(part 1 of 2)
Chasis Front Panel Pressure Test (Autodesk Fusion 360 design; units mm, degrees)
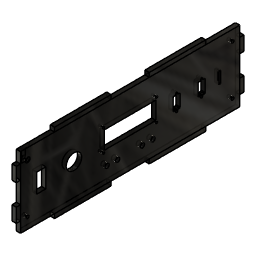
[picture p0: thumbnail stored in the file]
sketch "Sketch1" plane through (0, 0, 0) normal (1, 0, 0) x axis (0, 1, 0)
  line L1 (140.8306, 112.5808) -> (194.8306, 112.5808)
  line L2 (140.8306, 6.5808) -> (60.8306, 6.5808)
  line L3 (60.8306, 112.5808) -> (12.8306, 112.5808)
  line L4 (60.8306, 12.5808) -> (12.8306, 12.5808)
  line L5 (322.8306, 97.5808) -> (328.8306, 97.5808)
  line L6 (12.8306, 97.5808) -> (6.8306, 97.5808)
  line L7 (322.8306, 97.5808) -> (322.8306, 112.5808)
  line L8 (194.8306, 6.5808) -> (194.8306, 12.5808)
  line L9 (140.8306, 112.5808) -> (140.8306, 118.5808)
  line L10 (60.8306, 118.5808) -> (60.8306, 112.5808)
  line L11 (6.8306, 27.5808) -> (12.8306, 27.5808)
  line L12 (274.8306, 118.5808) -> (194.8306, 118.5808)
  line L13 (140.8306, 118.5808) -> (60.8306, 118.5808)
  line L14 (140.8306, 12.5808) -> (194.8306, 12.5808)
  line L15 (328.8306, 27.5808) -> (322.8306, 27.5808)
  line L16 (274.8306, 12.5808) -> (322.8306, 12.5808)
  line L17 (274.8306, 112.5808) -> (322.8306, 112.5808)
  line L18 (274.8306, 112.5808) -> (274.8306, 118.5808)
  line L19 (60.8306, 6.5808) -> (60.8306, 12.5808)
  line L20 (6.8306, 97.5808) -> (6.8306, 27.5808)
  line L21 (12.8306, 27.5808) -> (12.8306, 12.5808)
  line L22 (328.8306, 97.5808) -> (328.8306, 27.5808)
  line L23 (274.8306, 6.5808) -> (194.8306, 6.5808)
  line L24 (12.8306, 97.5808) -> (12.8306, 112.5808)
  line L25 (140.8306, 12.5808) -> (140.8306, 6.5808)
  line L26 (274.8306, 12.5808) -> (274.8306, 6.5808)
  line L27 (194.8306, 118.5808) -> (194.8306, 112.5808)
  line L28 (322.8306, 27.5808) -> (322.8306, 12.5808)
  line L29 (350, 62.5808) -> (328.8306, 62.5808)
  line L30 (167.8306, 0) -> (167.8306, 12.5808)
  point P34 (328.8306, 62.5808)
  point P36 (167.8306, 12.5808)
  point P26 (60.8306, 12.5808)
  point P27 (60.8306, 6.5808)
  point P8 (6.8306, 27.5808)
  point P20 (12.8306, 27.5808)
  point P3 (60.8306, 118.5808)
  point P10 (140.8306, 118.5808)
  point P6 (60.8306, 112.5808)
  point P9 (12.8306, 112.5808)
  point P19 (140.8306, 112.5808)
  point P23 (194.8306, 112.5808)
  point P32 (6.8306, 97.5808)
  point P16 (12.8306, 12.5808)
  point P2 (0, 0)
  point P1 (0, 0)
  point P37 (167.8306, 0)
  perpendicular L11 L21
  perpendicular L11 L20
  parallel L3 L13
  parallel L1 L3
  parallel L1 L12
  parallel L12 L17
  equal L9 L10
  equal L18 L27
  equal L5 L15
  equal L12 L13
  equal L21 L24
  parallel L2 L13
  parallel L12 L23
  parallel L16 L17
  parallel L1 L14
  parallel L21 L28
  parallel L7 L24
  equal L3 L17
  equal L10 L27
  equal L20 L22
  equal L7 L24
  equal L21 L28
  collinear L4 L14
  collinear L14 L16
  collinear L12 L13
  collinear L1 L3
  collinear L1 L17
  collinear L2 L23
  collinear L5 L6
  collinear L11 L15
  perpendicular L3 L24
  perpendicular L4 L21
  vertical L24
  midpoint L22 P34
  perpendicular L22 L29
  midpoint L14 P36
  perpendicular L14 L30
  dimension "d42" distance P26 P27 = 6
  dimension "d43" distance P8 P20 = 6
  dimension "d44" distance L20 L22 = 322
  dimension "d45" distance P3 P10 = 80
  dimension "d46" distance P6 P9 = 48
  dimension "d47" distance P19 P23 = 54
  dimension "d48" distance P3 P6 = 6
  dimension "d49" distance L16 L17 = 100
  dimension "d50" distance P8 P32 = 70
  dimension "d51" distance P16 P20 = 15
  dimension "d192" distance P2 L22 = 328.8306
  dimension "d195" distance P2 L29 = 62.5808
  dimension "d198" distance P1 P37 = 167.8306
extrude "Extrude3" new body sketch "Sketch1" profile of L1 L2 L3 L4 L5 L6 L7 L8 L9 L10 L11 L12 L13 L14 L15 L16 L17 L18 L19 L20 L21 L22 L23 L24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 along normal blind 6
sketch "Sketch2" plane through (6, 0, 0) normal (1, 0, 0) x axis (0, 1, 0)
  line L1 (194.8306, 6.5808) -> (194.8306, 12.5808)
  line L2 (274.8306, 6.5808) -> (194.8306, 6.5808)
  line L3 (274.8306, 12.5808) -> (274.8306, 6.5808)
  line L4 (322.8306, 12.5808) -> (274.8306, 12.5808)
  line L5 (322.8306, 27.5808) -> (322.8306, 12.5808)
  line L6 (328.8306, 27.5808) -> (322.8306, 27.5808)
  line L7 (328.8306, 97.5808) -> (328.8306, 27.5808)
  line L8 (322.8306, 97.5808) -> (328.8306, 97.5808)
  line L9 (322.8306, 112.5808) -> (322.8306, 97.5808)
  line L10 (274.8306, 112.5808) -> (322.8306, 112.5808)
  line L11 (274.8306, 118.5808) -> (274.8306, 112.5808)
  line L12 (194.8306, 118.5808) -> (274.8306, 118.5808)
  line L13 (194.8306, 112.5808) -> (194.8306, 118.5808)
  line L14 (140.8306, 112.5808) -> (194.8306, 112.5808)
  line L15 (140.8306, 118.5808) -> (140.8306, 112.5808)
  line L16 (60.8306, 118.5808) -> (140.8306, 118.5808)
  line L17 (60.8306, 112.5808) -> (60.8306, 118.5808)
  line L18 (12.8306, 112.5808) -> (60.8306, 112.5808)
  line L19 (12.8306, 97.5808) -> (12.8306, 112.5808)
  line L20 (6.8306, 97.5808) -> (12.8306, 97.5808)
  line L21 (6.8306, 27.5808) -> (6.8306, 97.5808)
  line L22 (12.8306, 27.5808) -> (6.8306, 27.5808)
  line L23 (12.8306, 12.5808) -> (12.8306, 27.5808)
  line L24 (60.8306, 12.5808) -> (12.8306, 12.5808)
  line L25 (60.8306, 6.5808) -> (60.8306, 12.5808)
  line L26 (140.8306, 6.5808) -> (60.8306, 6.5808)
  line L27 (140.8306, 12.5808) -> (140.8306, 6.5808)
  line L28 (194.8306, 12.5808) -> (140.8306, 12.5808)
  line L29 (204.3306, 80.0808) -> (131.3306, 80.0808)
  line L30 (204.3306, 55.0808) -> (204.3306, 80.0808)
  line L31 (131.3306, 55.0808) -> (204.3306, 55.0808)
  line L32 (131.3306, 80.0808) -> (131.3306, 55.0808)
  line L33 (48.6306, 76.0808) -> (35.6306, 76.0808)
  line L34 (48.6306, 49.0808) -> (48.6306, 76.0808)
  line L35 (35.6306, 49.0808) -> (48.6306, 49.0808)
  line L36 (35.6306, 76.0808) -> (35.6306, 49.0808)
  line L37 (167.8306, 12.5808) -> (167.8306, 112.5808)
  line L38 (6.8306, 62.5808) -> (328.8306, 62.5808)
  line L39 (204.3306, 55.0808) -> (131.3306, 80.0808)
  line L40 (204.3306, 80.0808) -> (131.3306, 55.0808)
  line L41 (167.8306, 55.0808) -> (167.8306, 80.0808)
  line L42 (204.3306, 67.5808) -> (131.3306, 67.5808)
  line L43 (99.4306, 62.5808) -> (88.4306, 62.5808)
  line L44 (48.6306, 62.5808) -> (35.6306, 62.5808)
  line L45 (185.3306, 33.8308) -> (150.3306, 33.8308)
  line L46 (167.8306, 44.7562) -> (167.8306, 33.8308)
  line L47 (130.3306, 83.0808) -> (205.3306, 83.0808)
  line L48 (130.3306, 52.0808) -> (130.3306, 83.0808)
  line L49 (205.3306, 52.0808) -> (130.3306, 52.0808)
  line L50 (205.3306, 83.0808) -> (205.3306, 52.0808)
  line L51 (130.3306, 52.0808) -> (205.3306, 83.0808)
  line L52 (205.3306, 52.0808) -> (130.3306, 83.0808)
  line L53 (351.4437, 121.1972) -> (351.4437, 118.8472)
  line L54 (351.4437, 115.8472) -> (351.4437, 113.4972)
  line L55 (351.4437, 115.8472) -> (349.7937, 115.8472)
  line L56 (370.1437, 121.1972) -> (370.1437, 118.8472)
  line L57 (351.4437, 118.8472) -> (349.7937, 118.8472)
  line L58 (360.7937, 122.2972) -> (360.7937, 117.3472)
  line L59 (349.7937, 117.3472) -> (360.7937, 117.3472)
  line L60 (370.1437, 115.8472) -> (370.1437, 113.4972)
  line L61 (369.0437, 122.2972) -> (352.5437, 122.2972)
  line L62 (352.5437, 112.3972) -> (369.0437, 112.3972)
  line L63 (370.1437, 115.8472) -> (371.7937, 115.8472)
  line L64 (370.1437, 118.8472) -> (371.7937, 118.8472)
  line L65 (348.2937, 117.3472) -> (349.7937, 117.3472)
  line L66 (373.2937, 117.3472) -> (371.7937, 117.3472)
  line L67 (272.9555, 53.2308) -> (270.6055, 53.2308)
  line L68 (274.0555, 54.3308) -> (274.0555, 70.8308)
  line L69 (272.9555, 71.9308) -> (270.6055, 71.9308)
  line L70 (269.1055, 75.0808) -> (269.1055, 73.5808)
  line L71 (267.6055, 53.2308) -> (265.2555, 53.2308)
  line L72 (270.6055, 53.2308) -> (270.6055, 51.5808)
  line L73 (270.6055, 71.9308) -> (270.6055, 73.5808)
  line L74 (267.6055, 53.2308) -> (267.6055, 51.5808)
  line L75 (269.1055, 50.0808) -> (269.1055, 51.5808)
  line L76 (267.6055, 71.9308) -> (265.2555, 71.9308)
  line L77 (274.0555, 62.5808) -> (269.1055, 62.5808)
  line L78 (267.6055, 71.9308) -> (267.6055, 73.5808)
  line L79 (264.1555, 70.8308) -> (264.1555, 54.3308)
  line L80 (269.1055, 73.5808) -> (269.1055, 62.5808)
  line L81 (295.8805, 70.6308) -> (293.4805, 70.6308)
  line L82 (295.8805, 54.5308) -> (295.8805, 70.6308)
  line L83 (293.4805, 54.5308) -> (295.8805, 54.5308)
  line L84 (293.4805, 70.6308) -> (293.4805, 54.5308)
  line L85 (269.1055, 75.0808) -> (269.1055, 73.5808)
  line L86 (272.9555, 71.9308) -> (270.6055, 71.9308)
  line L87 (269.1055, 50.0808) -> (269.1055, 51.5808)
  line L88 (272.9555, 53.2308) -> (270.6055, 53.2308)
  line L89 (269.1055, 73.5808) -> (269.1055, 62.5808)
  line L90 (274.0555, 62.5808) -> (269.1055, 62.5808)
  line L91 (267.6055, 53.2308) -> (265.2555, 53.2308)
  line L92 (270.6055, 71.9308) -> (270.6055, 73.5808)
  line L93 (267.6055, 71.9308) -> (265.2555, 71.9308)
  line L94 (267.6055, 71.9308) -> (267.6055, 73.5808)
  line L95 (270.6055, 53.2308) -> (270.6055, 51.5808)
  line L96 (274.0555, 54.3308) -> (274.0555, 70.8308)
  line L97 (264.1555, 70.8308) -> (264.1555, 54.3308)
  line L98 (267.6055, 53.2308) -> (267.6055, 51.5808)
  line L99 (295.8805, 62.5808) -> (293.4805, 62.5808)
  line L100 (294.6805, 70.6308) -> (294.6805, 54.5308)
  line L101 (228.6805, 70.8308) -> (228.6805, 54.3308)
  line L102 (233.6305, 73.5808) -> (233.6305, 62.5808)
  line L103 (237.4805, 71.9308) -> (235.1305, 71.9308)
  line L104 (232.1305, 71.9308) -> (232.1305, 73.5808)
  line L105 (238.5805, 54.3308) -> (238.5805, 70.8308)
  line L106 (232.1305, 71.9308) -> (232.1305, 73.5808)
  line L107 (228.6805, 70.8308) -> (228.6805, 54.3308)
  line L108 (238.5805, 62.5808) -> (233.6305, 62.5808)
  line L109 (232.1305, 71.9308) -> (229.7805, 71.9308)
  line L110 (238.5805, 54.3308) -> (238.5805, 70.8308)
  line L111 (232.1305, 71.9308) -> (229.7805, 71.9308)
  line L112 (233.6305, 75.0808) -> (233.6305, 73.5808)
  line L113 (232.1305, 53.2308) -> (229.7805, 53.2308)
  line L114 (232.1305, 53.2308) -> (229.7805, 53.2308)
  line L115 (233.6305, 50.0808) -> (233.6305, 51.5808)
  line L116 (237.4805, 71.9308) -> (235.1305, 71.9308)
  line L117 (233.6305, 75.0808) -> (233.6305, 73.5808)
  line L118 (232.1305, 53.2308) -> (232.1305, 51.5808)
  line L119 (235.1305, 71.9308) -> (235.1305, 73.5808)
  line L120 (235.1305, 71.9308) -> (235.1305, 73.5808)
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  point P43 (167.8306, 112.5808)
  point P44 (167.8306, 12.5808)
  point P45 (328.8306, 62.5808)
  point P46 (6.8306, 62.5808)
  point P47 (167.8306, 80.0808)
  point P48 (167.8306, 55.0808)
  point P49 (131.3306, 67.5808)
  point P50 (204.3306, 67.5808)
  point P42 (88.4306, 62.5808)
  point P51 (88.4306, 62.5808)
  point P53 (35.6306, 62.5808)
  point P54 (48.6306, 62.5808)
  point P35 (150.3306, 33.8308)
  point P55 (150.3306, 33.8308)
  point P36 (185.3306, 33.8308)
  point P56 (185.3306, 33.8308)
  point P57 (167.8306, 33.8308)
  point P63 (167.8306, 67.5808)
  point P59 (205.3306, 83.0808)
  point P64 (205.3306, 83.0808)
  point P62 (205.3306, 52.0808)
  point P65 (205.3306, 52.0808)
  point P60 (130.3306, 83.0808)
  point P66 (130.3306, 83.0808)
  point P61 (130.3306, 52.0808)
  point P67 (130.3306, 52.0808)
  point P94 (360.7937, 117.3472)
  point P96 (360.7937, 117.3472)
  point P68 (349.7937, 117.3472)
  point P95 (349.7937, 117.3472)
  point P69 (349.7937, 117.3472)
  point P80 (360.7937, 122.2972)
  point P77 (351.4437, 121.1972)
  point P92 (370.1437, 121.1972)
  point P83 (351.4437, 113.4972)
  point P89 (370.1437, 113.4972)
  point P72 (349.7937, 118.8472)
  point P93 (371.7937, 118.8472)
  point P76 (351.4437, 118.8472)
  point P90 (370.1437, 118.8472)
  point P79 (349.7937, 115.8472)
  point P87 (371.7937, 115.8472)
  point P70 (351.4437, 115.8472)
  point P91 (370.1437, 115.8472)
  point P97 (349.7937, 117.3472)
  point P88 (371.7937, 117.3472)
  point P99 (371.7937, 117.3472)
  point P119 (269.1055, 62.5808)
  point P128 (269.1055, 62.5808)
  point P107 (269.1055, 73.5808)
  point P127 (269.1055, 73.5808)
  point P101 (269.1055, 73.5808)
  point P112 (274.0555, 62.5808)
  point P110 (272.9555, 71.9308)
  point P124 (272.9555, 53.2308)
  point P116 (265.2555, 71.9308)
  point P121 (265.2555, 53.2308)
  point P106 (270.6055, 73.5808)
  point P118 (270.6055, 51.5808)
  point P104 (270.6055, 71.9308)
  point P122 (270.6055, 53.2308)
  point P111 (267.6055, 73.5808)
  point P125 (267.6055, 51.5808)
  point P108 (267.6055, 71.9308)
  point P126 (267.6055, 53.2308)
  point P130 (269.1055, 73.5808)
  point P123 (269.1055, 51.5808)
  point P132 (269.1055, 51.5808)
  point P149 (269.1055, 62.5808)
  point P168 (269.1055, 62.5808)
  point P142 (269.1055, 73.5808)
  point P158 (269.1055, 73.5808)
  point P162 (269.1055, 73.5808)
  point P151 (274.0555, 62.5808)
  point P139 (272.9555, 53.2308)
  point P146 (272.9555, 71.9308)
  point P143 (265.2555, 53.2308)
  point P155 (265.2555, 71.9308)
  point P148 (270.6055, 51.5808)
  point P156 (270.6055, 73.5808)
  point P144 (270.6055, 53.2308)
  point P163 (270.6055, 71.9308)
  point P145 (267.6055, 51.5808)
  point P150 (267.6055, 73.5808)
  point P141 (267.6055, 53.2308)
  point P159 (267.6055, 71.9308)
  point P165 (269.1055, 73.5808)
  point P138 (269.1055, 51.5808)
  point P167 (269.1055, 51.5808)
  point P171 (293.4805, 62.5808)
  point P172 (295.8805, 62.5808)
  point P173 (294.6805, 54.5308)
  point P174 (294.6805, 70.6308)
  point P186 (233.6305, 62.5808)
  point P205 (233.6305, 62.5808)
  point P179 (233.6305, 73.5808)
  point P195 (233.6305, 73.5808)
  point P199 (233.6305, 73.5808)
  point P188 (238.5805, 62.5808)
  point P202 (233.6305, 73.5808)
  point P175 (233.6305, 51.5808)
  point P204 (233.6305, 51.5808)
  point P213 (233.6305, 62.5808)
  point P226 (233.6305, 62.5808)
  point P209 (233.6305, 73.5808)
  point P227 (233.6305, 73.5808)
  point P230 (233.6305, 73.5808)
  point P238 (238.5805, 62.5808)
  point P232 (237.4805, 53.2308)
  point P236 (237.4805, 71.9308)
  point P217 (229.7805, 53.2308)
  point P220 (229.7805, 71.9308)
  point P223 (235.1305, 73.5808)
  point P231 (235.1305, 51.5808)
  point P207 (235.1305, 71.9308)
  point P229 (235.1305, 53.2308)
  point P208 (232.1305, 51.5808)
  point P214 (232.1305, 73.5808)
  point P216 (232.1305, 71.9308)
  point P235 (232.1305, 53.2308)
  point P219 (233.6305, 73.5808)
  point P212 (233.6305, 51.5808)
  point P225 (233.6305, 51.5808)
  point P241 (204.3306, 62.5808)
  point P243 (233.6305, 62.5808)
  point P30 (131.3306, 80.0808)
  point P31 (204.3306, 80.0808)
  point P33 (131.3306, 55.0808)
  point P34 (135.3306, 33.8308)
  point P37 (200.3306, 33.8308)
  point P38 (35.6306, 76.0808)
  point P39 (48.6306, 76.0808)
  point P41 (35.6306, 49.0808)
  point P78 (352.5437, 122.2972)
  point P86 (369.0437, 122.2972)
  point P98 (348.2937, 117.3472)
  point P100 (373.2937, 117.3472)
  point P115 (274.0555, 70.8308)
  point P120 (274.0555, 54.3308)
  point P131 (269.1055, 75.0808)
  point P133 (269.1055, 50.0808)
  point P134 (293.4805, 70.6308)
  point P135 (295.8805, 70.6308)
  point P137 (293.4805, 54.5308)
  point P140 (274.0555, 54.3308)
  point P154 (274.0555, 70.8308)
  point P169 (269.1055, 75.0808)
  point P170 (269.1055, 50.0808)
  point P183 (237.4805, 71.9308)
  point P200 (235.1305, 71.9308)
  point P177 (238.5805, 54.3308)
  point P191 (238.5805, 70.8308)
  point P206 (233.6305, 75.0808)
  point P222 (233.6305, 50.0808)
  point P218 (238.5805, 70.8308)
  point P233 (238.5805, 54.3308)
  point P228 (233.6305, 75.0808)
  point P240 (233.6305, 50.0808)
  point P242 (229.9056, 62.5808)
  horizontal L29
  vertical L30
  horizontal L31
  vertical L32
  horizontal L33
  vertical L34
  horizontal L35
  vertical L36
  midpoint L14 P43
  midpoint L28 P44
  midpoint L7 P45
  midpoint L21 P46
  midpoint L29 P47
  midpoint L31 P48
  midpoint L32 P49
  midpoint L30 P50
  coincident P42 P51
  horizontal L43
  collinear L38 L43
  midpoint L36 P53
  midpoint L34 P54
  collinear L38 L44
  coincident P35 P55
  coincident P36 P56
  parallel L26 L45
  midpoint L45 P57
  perpendicular L45 L46
  collinear L37 L46
  collinear L37 L41
  horizontal L47
  perpendicular L47 L48
  parallel L47 L49
  parallel L48 L50
  coincident L51 P63
  coincident L52 P63
  midpoint L39 P63
  coincident P59 P64
  coincident P62 P65
  coincident P60 P66
  coincident P61 P67
  horizontal L62
  parallel L61 L62
  coincident P94 P96
  coincident P68 P95
  coincident P68 P69
  midpoint P80 L61
  perpendicular L58 L61
  symmetric P77 P92 L58
  symmetric P83 P89 L58
  symmetric P72 P93 L58
  symmetric P76 P90 L58
  symmetric P79 P87 L58
  symmetric P70 P91 L58
  equal L53 L54
  equal L61 L62
  coincident P68 P97
  parallel L59 L65
  coincident P88 P99
  perpendicular L56 L66
  parallel L68 L79
  coincident P119 P128
  coincident P107 P127
  coincident P101 P107
  midpoint P112 L68
  perpendicular L68 L77
  symmetric P110 P124 L77
  symmetric P116 P121 L77
  symmetric P106 P118 L77
  symmetric P104 P122 L77
  symmetric P111 P125 L77
  symmetric P108 P126 L77
  equal L69 L76
  equal L68 L79
  coincident P107 P130
  parallel L70 L80
  coincident P123 P132
  perpendicular L67 L75
  horizontal L81
  vertical L82
  horizontal L83
  vertical L84
  parallel L96 L97
  coincident P149 P168
  coincident P142 P158
  coincident P158 P162
  midpoint P151 L96
  perpendicular L90 L96
  symmetric P139 P146 L90
  symmetric P143 P155 L90
  symmetric P148 P156 L90
  symmetric P144 P163 L90
  symmetric P145 P150 L90
  symmetric P141 P159 L90
  equal L86 L93
  equal L96 L97
  coincident P158 P165
  parallel L85 L89
  coincident P138 P167
  perpendicular L87 L88
  midpoint L84 P171
  midpoint L82 P172
  collinear L77 L99
  midpoint L83 P173
  midpoint L81 P174
  parallel L105 L107
  coincident P186 P205
  coincident P179 P195
  coincident P195 P199
  midpoint P188 L105
  equal L103 L109
  equal L105 L107
  coincident P195 P202
  parallel L102 L112
  coincident P175 P204
  parallel L101 L110
  coincident P213 P226
  coincident P209 P227
  coincident P227 P230
  midpoint P238 L110
  perpendicular L108 L110
  symmetric P232 P236 L108
  symmetric P217 P220 L108
  symmetric P223 P231 L108
  symmetric P207 P229 L108
  symmetric P208 P214 L108
  symmetric P216 P235 L108
  equal L111 L116
  equal L101 L110
  coincident P219 P227
  coincident P212 P225
  coincident L30 P241
  coincident L38 P241
  coincident P213 P243
  dimension "d56" distance P30 P31 = 73
  dimension "d57" distance P30 P33 = 25
  dimension "d58" diameter = 6
  dimension "d59" diameter = 6
  dimension "d60" distance P34 P35 = 15
  dimension "d61" diameter = 6
  dimension "d62" diameter = 6
  dimension "d63" distance P36 P37 = 15
  dimension "d64" distance P35 P36 = 35
  dimension "d65" distance P38 P39 = 13
  dimension "d66" distance P38 P41 = 27
  dimension "d67" diameter = 22
  dimension "d68" distance L31 L45 = 21.25 (= "d75 / 2")
  dimension "d69" distance L38 L42 = 5
  dimension "d73" distance L21 L36 = 28.8
  dimension "d74" distance L34 P42 = 39.8 (= "28.8 mm + 11 mm")
  dimension "d75" distance L28 L31 = 42.5
  dimension "d76" distance P61 P62 = 75
  dimension "d77" distance P60 P61 = 31
  dimension "d78" diameter = 3
  dimension "d79" diameter = 3
  dimension "d80" diameter = 3
  dimension "d81" diameter = 3
  dimension "d82" distance P95 P96 = 11
  dimension "d83" diameter = 3
  dimension "d84" distance L59 L61 = 4.95
  dimension "d85" distance P76 P77 = 2.35
  dimension "d86" radius = 1.1
  dimension "d87" distance P78 P86 = 16.5
  dimension "d88" distance L54 L60 = 18.7
  dimension "d89" distance P69 P88 = 22
  dimension "d90" distance L61 L62 = 9.9
  dimension "d91" distance P98 P100 = 25
  dimension "d92" distance P127 P128 = 11
  dimension "d93" diameter = 3
  dimension "d94" distance L68 L80 = 4.95
  dimension "d95" distance P104 P110 = 2.35
  dimension "d96" radius = 1.1
  dimension "d97" distance P115 P120 = 16.5
  dimension "d98" distance L71 L76 = 18.7
  dimension "d99" distance P101 P123 = 22
  dimension "d100" distance L68 L79 = 9.9
  dimension "d101" distance P131 P133 = 25
  dimension "d102" distance P134 P135 = 2.4
  dimension "d103" distance P134 P137 = 16.1
  dimension "d104" distance P142 P168 = 11
  dimension "d105" diameter = 3
  dimension "d106" distance L89 L96 = 4.95
  dimension "d107" distance P146 P163 = 2.35
  dimension "d108" radius = 1.1
  dimension "d109" distance P140 P154 = 16.5
  dimension "d110" distance L91 L93 = 18.7
  dimension "d111" distance P138 P162 = 22
  dimension "d112" distance L96 L97 = 9.9
  dimension "d113" distance P169 P170 = 25
  dimension "d125" distance L89 L100 = 25.575
  dimension "d126" distance P179 P205 = 11
  dimension "d127" diameter = 3
  dimension "d128" distance L102 L105 = 4.95
  dimension "d129" distance P183 P200 = 2.35
  dimension "d130" radius = 1.1
  dimension "d131" distance P177 P191 = 16.5
  dimension "d132" distance L109 L113 = 18.7
  dimension "d133" distance P175 P199 = 22
  dimension "d134" distance L105 L107 = 9.9
  dimension "d135" distance P206 P222 = 25
  dimension "d136" distance P209 P226 = 11
  dimension "d137" diameter = 3
  dimension "d138" distance = 4.95
  dimension "d139" distance P207 P236 = 2.35
  dimension "d140" radius = 1.1
  dimension "d141" distance P218 P233 = 16.5
  dimension "d142" distance L111 L114 = 18.7
  dimension "d143" distance P212 P230 = 22
  dimension "d144" distance L101 L110 = 9.9
  dimension "d145" distance P228 P240 = 25
  dimension "d146" distance L80 L102 = 35.475
  dimension "d147" distance P241 P242 = 25.575
extrude "Extrude4" cut sketch "Sketch2" against normal blind 6
sketch "Sketch4" plane through (6, 0, 0) normal (1, 0, 0) x axis (0, 1, 0)
  line L1 (12.8306, 27.5808) -> (6.8306, 27.5808)
  line L2 (12.8306, 12.5808) -> (12.8306, 27.5808)
  line L3 (60.8306, 12.5808) -> (12.8306, 12.5808)
  line L4 (60.8306, 6.5808) -> (60.8306, 12.5808)
  line L5 (140.8306, 6.5808) -> (60.8306, 6.5808)
  line L6 (140.8306, 12.5808) -> (140.8306, 6.5808)
  line L7 (194.8306, 12.5808) -> (140.8306, 12.5808)
  line L8 (194.8306, 6.5808) -> (194.8306, 12.5808)
  line L9 (274.8306, 6.5808) -> (194.8306, 6.5808)
  line L10 (274.8306, 12.5808) -> (274.8306, 6.5808)
  line L11 (322.8306, 12.5808) -> (274.8306, 12.5808)
  line L12 (322.8306, 27.5808) -> (322.8306, 12.5808)
  line L13 (328.8306, 27.5808) -> (322.8306, 27.5808)
  line L14 (328.8306, 97.5808) -> (328.8306, 27.5808)
  line L15 (322.8306, 97.5808) -> (328.8306, 97.5808)
  line L16 (322.8306, 112.5808) -> (322.8306, 97.5808)
  line L17 (274.8306, 112.5808) -> (322.8306, 112.5808)
  line L18 (274.8306, 118.5808) -> (274.8306, 112.5808)
  line L19 (194.8306, 118.5808) -> (274.8306, 118.5808)
  line L20 (194.8306, 112.5808) -> (194.8306, 118.5808)
  line L21 (140.8306, 112.5808) -> (194.8306, 112.5808)
  line L22 (140.8306, 118.5808) -> (140.8306, 112.5808)
  line L23 (60.8306, 118.5808) -> (140.8306, 118.5808)
  line L24 (60.8306, 112.5808) -> (60.8306, 118.5808)
  line L25 (12.8306, 112.5808) -> (60.8306, 112.5808)
  line L26 (12.8306, 97.5808) -> (12.8306, 112.5808)
  line L27 (6.8306, 97.5808) -> (12.8306, 97.5808)
  line L28 (6.8306, 27.5808) -> (6.8306, 97.5808)
  line L29 (235.1305, 51.5808) -> (235.1305, 53.2308)
  line L30 (232.1305, 53.2308) -> (232.1305, 51.5808)
  line L31 (229.7805, 53.2308) -> (232.1305, 53.2308)
  line L32 (228.6805, 70.8308) -> (228.6805, 54.3308)
  line L33 (232.1305, 71.9308) -> (229.7805, 71.9308)
  line L34 (232.1305, 73.5808) -> (232.1305, 71.9308)
  line L35 (235.1305, 71.9308) -> (235.1305, 73.5808)
  line L36 (237.4805, 71.9308) -> (235.1305, 71.9308)
  line L37 (238.5805, 54.3308) -> (238.5805, 70.8308)
  line L38 (235.1305, 53.2308) -> (237.4805, 53.2308)
  line L39 (204.3306, 55.0808) -> (204.3306, 80.0808)
  line L40 (131.3306, 55.0808) -> (204.3306, 55.0808)
  line L41 (131.3306, 80.0808) -> (131.3306, 55.0808)
  line L42 (204.3306, 80.0808) -> (131.3306, 80.0808)
  line L43 (270.6055, 53.2308) -> (272.9555, 53.2308)
  line L44 (270.6055, 51.5808) -> (270.6055, 53.2308)
  line L45 (267.6055, 53.2308) -> (267.6055, 51.5808)
  line L46 (265.2555, 53.2308) -> (267.6055, 53.2308)
  line L47 (264.1555, 70.8308) -> (264.1555, 54.3308)
  line L48 (267.6055, 71.9308) -> (265.2555, 71.9308)
  line L49 (267.6055, 73.5808) -> (267.6055, 71.9308)
  line L50 (270.6055, 71.9308) -> (270.6055, 73.5808)
  line L51 (272.9555, 71.9308) -> (270.6055, 71.9308)
  line L52 (274.0555, 54.3308) -> (274.0555, 70.8308)
  line L53 (48.6306, 49.0808) -> (48.6306, 76.0808)
  line L54 (35.6306, 49.0808) -> (48.6306, 49.0808)
  line L55 (35.6306, 76.0808) -> (35.6306, 49.0808)
  line L56 (48.6306, 76.0808) -> (35.6306, 76.0808)
  line L57 (295.8805, 54.5308) -> (295.8805, 70.6308)
  line L58 (293.4805, 54.5308) -> (295.8805, 54.5308)
  line L59 (293.4805, 70.6308) -> (293.4805, 54.5308)
  line L60 (295.8805, 70.6308) -> (293.4805, 70.6308)
  line L61 (322.8306, 47.5808) -> (328.8306, 47.5808)
  line L62 (322.8306, 47.5808) -> (322.8306, 77.5808)
  line L63 (322.8306, 77.5808) -> (328.8306, 77.5808)
  line L64 (12.8306, 47.5808) -> (6.8306, 47.5808)
  line L65 (12.8306, 47.5808) -> (12.8306, 77.5808)
  line L66 (12.8306, 77.5808) -> (6.8306, 77.5808)
  line L67 (328.8306, 47.5808) -> (328.8306, 77.5808)
  line L68 (6.8306, 47.5808) -> (6.8306, 77.5808)
  arc A1 centre (233.6305, 51.5808) radius 1.5 clockwise from (235.1305, 51.5808) to (232.1305, 51.5808)
  arc A2 centre (229.7805, 54.3308) radius 1.1 clockwise from (229.7805, 53.2308) to (228.6805, 54.3308)
  arc A3 centre (229.7805, 70.8308) radius 1.1 clockwise from (228.6805, 70.8308) to (229.7805, 71.9308)
  arc A4 centre (233.6305, 73.5808) radius 1.5 clockwise from (232.1305, 73.5808) to (235.1305, 73.5808)
  arc A5 centre (237.4805, 70.8308) radius 1.1 clockwise from (237.4805, 71.9308) to (238.5805, 70.8308)
  arc A6 centre (237.4805, 54.3308) radius 1.1 clockwise from (238.5805, 54.3308) to (237.4805, 53.2308)
  circle C1 centre (130.3306, 52.0808) radius 1.5
  circle C2 centre (135.3306, 33.8308) radius 3
  circle C3 centre (150.3306, 33.8308) radius 3
  circle C4 centre (130.3306, 83.0808) radius 1.5
  arc A7 centre (269.1055, 51.5808) radius 1.5 clockwise from (270.6055, 51.5808) to (267.6055, 51.5808)
  arc A8 centre (265.2555, 54.3308) radius 1.1 clockwise from (265.2555, 53.2308) to (264.1555, 54.3308)
  arc A9 centre (265.2555, 70.8308) radius 1.1 clockwise from (264.1555, 70.8308) to (265.2555, 71.9308)
  arc A10 centre (269.1055, 73.5808) radius 1.5 clockwise from (267.6055, 73.5808) to (270.6055, 73.5808)
  arc A11 centre (272.9555, 70.8308) radius 1.1 clockwise from (272.9555, 71.9308) to (274.0555, 70.8308)
  arc A12 centre (272.9555, 54.3308) radius 1.1 clockwise from (274.0555, 54.3308) to (272.9555, 53.2308)
  circle C5 centre (205.3306, 83.0808) radius 1.5
  circle C6 centre (200.3306, 33.8308) radius 3
  circle C7 centre (88.4306, 62.5808) radius 11
  circle C8 centre (185.3306, 33.8308) radius 3
  circle C9 centre (205.3306, 52.0808) radius 1.5
  point P104 (322.8306, 47.5808)
  point P105 (328.8306, 47.5808)
  point P106 (322.8306, 77.5808)
  point P110 (328.8306, 77.5808)
  perpendicular L61 L67
  perpendicular L64 L68
  dimension "d203" distance P104 P105 = 6
  dimension "d204" distance P106 P110 = 6
extrude "Extrude6" cut sketch "Sketch4" profile of L14 L28 L61 L62 L63 L64 L65 L66 L67 L68 against normal blind 15
sketch "Sketch5" plane through (6, 0, 0) normal (1, 0, 0) x axis (0, 1, 0)
  line L1 (6.8306, 47.5808) -> (12.8306, 47.5808)
  line L2 (6.8306, 27.5808) -> (6.8306, 47.5808)
  line L3 (12.8306, 27.5808) -> (6.8306, 27.5808)
  line L4 (12.8306, 12.5808) -> (12.8306, 27.5808)
  line L5 (60.8306, 12.5808) -> (12.8306, 12.5808)
  line L6 (60.8306, 6.5808) -> (60.8306, 12.5808)
  line L7 (140.8306, 6.5808) -> (60.8306, 6.5808)
  line L8 (140.8306, 12.5808) -> (140.8306, 6.5808)
  line L9 (194.8306, 12.5808) -> (140.8306, 12.5808)
  line L10 (194.8306, 6.5808) -> (194.8306, 12.5808)
  line L11 (274.8306, 6.5808) -> (194.8306, 6.5808)
  line L12 (274.8306, 12.5808) -> (274.8306, 6.5808)
  line L13 (322.8306, 12.5808) -> (274.8306, 12.5808)
  line L14 (322.8306, 27.5808) -> (322.8306, 12.5808)
  line L15 (328.8306, 27.5808) -> (322.8306, 27.5808)
  line L16 (328.8306, 47.5808) -> (328.8306, 27.5808)
  line L17 (322.8306, 47.5808) -> (328.8306, 47.5808)
  line L18 (322.8306, 77.5808) -> (322.8306, 47.5808)
  line L19 (328.8306, 77.5808) -> (322.8306, 77.5808)
  line L20 (328.8306, 97.5808) -> (328.8306, 77.5808)
  line L21 (322.8306, 97.5808) -> (328.8306, 97.5808)
  line L22 (322.8306, 112.5808) -> (322.8306, 97.5808)
  line L23 (274.8306, 112.5808) -> (322.8306, 112.5808)
  line L24 (274.8306, 118.5808) -> (274.8306, 112.5808)
  line L25 (194.8306, 118.5808) -> (274.8306, 118.5808)
  line L26 (194.8306, 112.5808) -> (194.8306, 118.5808)
  line L27 (140.8306, 112.5808) -> (194.8306, 112.5808)
  line L28 (140.8306, 118.5808) -> (140.8306, 112.5808)
  line L29 (60.8306, 118.5808) -> (140.8306, 118.5808)
  line L30 (60.8306, 112.5808) -> (60.8306, 118.5808)
  line L31 (12.8306, 112.5808) -> (60.8306, 112.5808)
  line L32 (12.8306, 97.5808) -> (12.8306, 112.5808)
  line L33 (6.8306, 97.5808) -> (12.8306, 97.5808)
  line L34 (6.8306, 77.5808) -> (6.8306, 97.5808)
  line L35 (12.8306, 77.5808) -> (6.8306, 77.5808)
  line L36 (12.8306, 47.5808) -> (12.8306, 77.5808)
  line L37 (235.1305, 51.5808) -> (235.1305, 53.2308)
  line L38 (232.1305, 53.2308) -> (232.1305, 51.5808)
  line L39 (229.7805, 53.2308) -> (232.1305, 53.2308)
  line L40 (228.6805, 70.8308) -> (228.6805, 54.3308)
  line L41 (232.1305, 71.9308) -> (229.7805, 71.9308)
  line L42 (232.1305, 73.5808) -> (232.1305, 71.9308)
  line L43 (235.1305, 71.9308) -> (235.1305, 73.5808)
  line L44 (237.4805, 71.9308) -> (235.1305, 71.9308)
  line L45 (238.5805, 54.3308) -> (238.5805, 70.8308)
  line L46 (235.1305, 53.2308) -> (237.4805, 53.2308)
  line L47 (204.3306, 55.0808) -> (204.3306, 80.0808)
  line L48 (131.3306, 55.0808) -> (204.3306, 55.0808)
  line L49 (131.3306, 80.0808) -> (131.3306, 55.0808)
  line L50 (204.3306, 80.0808) -> (131.3306, 80.0808)
  line L51 (270.6055, 53.2308) -> (272.9555, 53.2308)
  line L52 (270.6055, 51.5808) -> (270.6055, 53.2308)
  line L53 (267.6055, 53.2308) -> (267.6055, 51.5808)
  line L54 (265.2555, 53.2308) -> (267.6055, 53.2308)
  line L55 (264.1555, 70.8308) -> (264.1555, 54.3308)
  line L56 (267.6055, 71.9308) -> (265.2555, 71.9308)
  line L57 (267.6055, 73.5808) -> (267.6055, 71.9308)
  line L58 (270.6055, 71.9308) -> (270.6055, 73.5808)
  line L59 (272.9555, 71.9308) -> (270.6055, 71.9308)
  line L60 (274.0555, 54.3308) -> (274.0555, 70.8308)
  line L61 (48.6306, 49.0808) -> (48.6306, 76.0808)
  line L62 (35.6306, 49.0808) -> (48.6306, 49.0808)
  line L63 (35.6306, 76.0808) -> (35.6306, 49.0808)
  line L64 (48.6306, 76.0808) -> (35.6306, 76.0808)
  line L65 (295.8805, 54.5308) -> (295.8805, 70.6308)
  line L66 (293.4805, 54.5308) -> (295.8805, 54.5308)
  line L67 (293.4805, 70.6308) -> (293.4805, 54.5308)
  line L68 (295.8805, 70.6308) -> (293.4805, 70.6308)
  line L69 (22.8306, 112.5808) -> (12.8306, 112.5808)
  line L70 (22.8306, 97.5808) -> (22.8306, 112.5808)
  line L71 (12.8306, 97.5808) -> (22.8306, 97.5808)
  line L72 (12.8306, 112.5808) -> (12.8306, 97.5808)
  line L73 (322.8306, 62.5808) -> (12.8306, 62.5808)
  line L74 (167.8306, 12.5808) -> (167.8306, 112.5808)
  arc A1 centre (233.6305, 51.5808) radius 1.5 clockwise from (235.1305, 51.5808) to (232.1305, 51.5808)
  arc A2 centre (229.7805, 54.3308) radius 1.1 clockwise from (229.7805, 53.2308) to (228.6805, 54.3308)
  arc A3 centre (229.7805, 70.8308) radius 1.1 clockwise from (228.6805, 70.8308) to (229.7805, 71.9308)
  arc A4 centre (233.6305, 73.5808) radius 1.5 clockwise from (232.1305, 73.5808) to (235.1305, 73.5808)
  arc A5 centre (237.4805, 70.8308) radius 1.1 clockwise from (237.4805, 71.9308) to (238.5805, 70.8308)
  arc A6 centre (237.4805, 54.3308) radius 1.1 clockwise from (238.5805, 54.3308) to (237.4805, 53.2308)
  circle C1 centre (130.3306, 52.0808) radius 1.5
  circle C2 centre (135.3306, 33.8308) radius 3
  circle C3 centre (150.3306, 33.8308) radius 3
  circle C4 centre (130.3306, 83.0808) radius 1.5
  arc A7 centre (269.1055, 51.5808) radius 1.5 clockwise from (270.6055, 51.5808) to (267.6055, 51.5808)
  arc A8 centre (265.2555, 54.3308) radius 1.1 clockwise from (265.2555, 53.2308) to (264.1555, 54.3308)
  arc A9 centre (265.2555, 70.8308) radius 1.1 clockwise from (264.1555, 70.8308) to (265.2555, 71.9308)
  arc A10 centre (269.1055, 73.5808) radius 1.5 clockwise from (267.6055, 73.5808) to (270.6055, 73.5808)
  arc A11 centre (272.9555, 70.8308) radius 1.1 clockwise from (272.9555, 71.9308) to (274.0555, 70.8308)
  arc A12 centre (272.9555, 54.3308) radius 1.1 clockwise from (274.0555, 54.3308) to (272.9555, 53.2308)
  circle C5 centre (205.3306, 83.0808) radius 1.5
  circle C6 centre (200.3306, 33.8308) radius 3
  circle C7 centre (88.4306, 62.5808) radius 11
  circle C8 centre (185.3306, 33.8308) radius 3
  circle C9 centre (205.3306, 52.0808) radius 1.5
  circle C10 centre (22.8306, 97.5808) radius 2.05
  circle C11 centre (312.8306, 97.5808) radius 2.05
  circle C12 centre (22.8306, 27.5808) radius 2.05
  circle C13 centre (312.8306, 27.5808) radius 2.05
  point P33 (12.8306, 112.5808)
  point P103 (12.8306, 112.5808)
  point P105 (22.8306, 97.5808)
  point P107 (22.8306, 97.5808)
  point P108 (12.8306, 62.5808)
  point P109 (322.8306, 62.5808)
  point P110 (167.8306, 112.5808)
  point P111 (167.8306, 12.5808)
  point P104 (22.8306, 112.5808)
  point P106 (12.8306, 97.5808)
  horizontal L69
  vertical L70
  horizontal L71
  vertical L72
  coincident P33 P103
  coincident P105 P107
  midpoint L36 P108
  midpoint L18 P109
  midpoint L27 P110
  midpoint L9 P111
  symmetric C10 L74 C11
  symmetric C10 L73 C12
  symmetric L73 C11 C13
  dimension "d207" distance P103 P104 = 10
  dimension "d208" distance P103 P106 = 15
  dimension "d209" diameter C10 = 4.1
extrude "Extrude7" cut sketch "Sketch5" profile of C10 C11 C12 C13 no distance stored
sketch "Sketch6" plane through (6, 0, 0) normal (1, 0, 0) x axis (0, 1, 0)
  line L1 (6.8306, 47.5808) -> (12.8306, 47.5808)
  line L2 (6.8306, 27.5808) -> (6.8306, 47.5808)
  line L3 (12.8306, 27.5808) -> (6.8306, 27.5808)
  line L4 (12.8306, 12.5808) -> (12.8306, 27.5808)
  line L5 (60.8306, 12.5808) -> (12.8306, 12.5808)
  line L6 (60.8306, 6.5808) -> (60.8306, 12.5808)
  line L7 (140.8306, 6.5808) -> (60.8306, 6.5808)
  line L8 (140.8306, 12.5808) -> (140.8306, 6.5808)
  line L9 (194.8306, 12.5808) -> (140.8306, 12.5808)
  line L10 (194.8306, 6.5808) -> (194.8306, 12.5808)
  line L11 (274.8306, 6.5808) -> (194.8306, 6.5808)
  line L12 (274.8306, 12.5808) -> (274.8306, 6.5808)
  line L13 (322.8306, 12.5808) -> (274.8306, 12.5808)
  line L14 (322.8306, 27.5808) -> (322.8306, 12.5808)
  line L15 (328.8306, 27.5808) -> (322.8306, 27.5808)
  line L16 (328.8306, 47.5808) -> (328.8306, 27.5808)
  line L17 (322.8306, 47.5808) -> (328.8306, 47.5808)
  line L18 (322.8306, 77.5808) -> (322.8306, 47.5808)
  line L19 (328.8306, 77.5808) -> (322.8306, 77.5808)
  line L20 (328.8306, 97.5808) -> (328.8306, 77.5808)
  line L21 (322.8306, 97.5808) -> (328.8306, 97.5808)
  line L22 (322.8306, 112.5808) -> (322.8306, 97.5808)
  line L23 (274.8306, 112.5808) -> (322.8306, 112.5808)
  line L24 (274.8306, 118.5808) -> (274.8306, 112.5808)
  line L25 (194.8306, 118.5808) -> (274.8306, 118.5808)
  line L26 (194.8306, 112.5808) -> (194.8306, 118.5808)
  line L27 (140.8306, 112.5808) -> (194.8306, 112.5808)
  line L28 (140.8306, 118.5808) -> (140.8306, 112.5808)
  line L29 (60.8306, 118.5808) -> (140.8306, 118.5808)
  line L30 (60.8306, 112.5808) -> (60.8306, 118.5808)
  line L31 (12.8306, 112.5808) -> (60.8306, 112.5808)
  line L32 (12.8306, 97.5808) -> (12.8306, 112.5808)
  line L33 (6.8306, 97.5808) -> (12.8306, 97.5808)
  line L34 (6.8306, 77.5808) -> (6.8306, 97.5808)
  line L35 (12.8306, 77.5808) -> (6.8306, 77.5808)
  line L36 (12.8306, 47.5808) -> (12.8306, 77.5808)
  line L37 (235.1305, 51.5808) -> (235.1305, 53.2308)
  line L38 (232.1305, 53.2308) -> (232.1305, 51.5808)
  line L39 (229.7805, 53.2308) -> (232.1305, 53.2308)
  line L40 (228.6805, 70.8308) -> (228.6805, 54.3308)
  line L41 (232.1305, 71.9308) -> (229.7805, 71.9308)
  line L42 (232.1305, 73.5808) -> (232.1305, 71.9308)
  line L43 (235.1305, 71.9308) -> (235.1305, 73.5808)
  line L44 (237.4805, 71.9308) -> (235.1305, 71.9308)
  line L45 (238.5805, 54.3308) -> (238.5805, 70.8308)
  line L46 (235.1305, 53.2308) -> (237.4805, 53.2308)
  line L47 (204.3306, 55.0808) -> (204.3306, 80.0808)
  line L48 (131.3306, 55.0808) -> (204.3306, 55.0808)
  line L49 (131.3306, 80.0808) -> (131.3306, 55.0808)
  line L50 (204.3306, 80.0808) -> (131.3306, 80.0808)
  line L51 (270.6055, 53.2308) -> (272.9555, 53.2308)
  line L52 (270.6055, 51.5808) -> (270.6055, 53.2308)
  line L53 (267.6055, 53.2308) -> (267.6055, 51.5808)
  line L54 (265.2555, 53.2308) -> (267.6055, 53.2308)
  line L55 (264.1555, 70.8308) -> (264.1555, 54.3308)
  line L56 (267.6055, 71.9308) -> (265.2555, 71.9308)
  line L57 (267.6055, 73.5808) -> (267.6055, 71.9308)
  line L58 (270.6055, 71.9308) -> (270.6055, 73.5808)
  line L59 (272.9555, 71.9308) -> (270.6055, 71.9308)
  line L60 (274.0555, 54.3308) -> (274.0555, 70.8308)
  line L61 (48.6306, 49.0808) -> (48.6306, 76.0808)
  line L62 (35.6306, 49.0808) -> (48.6306, 49.0808)
  line L63 (35.6306, 76.0808) -> (35.6306, 49.0808)
  line L64 (48.6306, 76.0808) -> (35.6306, 76.0808)
  line L65 (295.8805, 54.5308) -> (295.8805, 70.6308)
  line L66 (293.4805, 54.5308) -> (295.8805, 54.5308)
  line L67 (293.4805, 70.6308) -> (293.4805, 54.5308)
  line L68 (295.8805, 70.6308) -> (293.4805, 70.6308)
  circle C1 centre (22.8306, 27.5808) radius 2.05
  circle C2 centre (312.8306, 27.5808) radius 2.05
  circle C3 centre (22.8306, 97.5808) radius 2.05
  circle C4 centre (312.8306, 97.5808) radius 2.05
  arc A1 centre (233.6305, 51.5808) radius 1.5 clockwise from (235.1305, 51.5808) to (232.1305, 51.5808)
  arc A2 centre (229.7805, 54.3308) radius 1.1 clockwise from (229.7805, 53.2308) to (228.6805, 54.3308)
  arc A3 centre (229.7805, 70.8308) radius 1.1 clockwise from (228.6805, 70.8308) to (229.7805, 71.9308)
  arc A4 centre (233.6305, 73.5808) radius 1.5 clockwise from (232.1305, 73.5808) to (235.1305, 73.5808)
  arc A5 centre (237.4805, 70.8308) radius 1.1 clockwise from (237.4805, 71.9308) to (238.5805, 70.8308)
  arc A6 centre (237.4805, 54.3308) radius 1.1 clockwise from (238.5805, 54.3308) to (237.4805, 53.2308)
  circle C5 centre (130.3306, 52.0808) radius 1.5
  circle C6 centre (135.3306, 33.8308) radius 3
  circle C7 centre (150.3306, 33.8308) radius 3
  circle C8 centre (130.3306, 83.0808) radius 1.5
  arc A7 centre (269.1055, 51.5808) radius 1.5 clockwise from (270.6055, 51.5808) to (267.6055, 51.5808)
  arc A8 centre (265.2555, 54.3308) radius 1.1 clockwise from (265.2555, 53.2308) to (264.1555, 54.3308)
  arc A9 centre (265.2555, 70.8308) radius 1.1 clockwise from (264.1555, 70.8308) to (265.2555, 71.9308)
  arc A10 centre (269.1055, 73.5808) radius 1.5 clockwise from (267.6055, 73.5808) to (270.6055, 73.5808)
  arc A11 centre (272.9555, 70.8308) radius 1.1 clockwise from (272.9555, 71.9308) to (274.0555, 70.8308)
  arc A12 centre (272.9555, 54.3308) radius 1.1 clockwise from (274.0555, 54.3308) to (272.9555, 53.2308)
  circle C9 centre (205.3306, 83.0808) radius 1.5
  circle C10 centre (200.3306, 33.8308) radius 3
  circle C11 centre (88.4306, 62.5808) radius 11
  circle C12 centre (185.3306, 33.8308) radius 3
  circle C13 centre (205.3306, 52.0808) radius 1.5
  circle C14 centre (22.8306, 97.5808) radius 3.424
  concentric C3 C14
  dimension "d211" diameter C14 = 6.848
extrude "Extrude8" add sketch "Sketch6" profile of C3 C14 along normal blind 0.01
sketch "Sketch7" plane through (6, 0, 0) normal (1, 0, 0) x axis (0, 1, 0)
  line L1 (6.8306, 47.5808) -> (12.8306, 47.5808)
  line L2 (6.8306, 27.5808) -> (6.8306, 47.5808)
  line L3 (12.8306, 27.5808) -> (6.8306, 27.5808)
  line L4 (12.8306, 12.5808) -> (12.8306, 27.5808)
  line L5 (60.8306, 12.5808) -> (12.8306, 12.5808)
  line L6 (60.8306, 6.5808) -> (60.8306, 12.5808)
  line L7 (140.8306, 6.5808) -> (60.8306, 6.5808)
  line L8 (140.8306, 12.5808) -> (140.8306, 6.5808)
  line L9 (194.8306, 12.5808) -> (140.8306, 12.5808)
  line L10 (194.8306, 6.5808) -> (194.8306, 12.5808)
  line L11 (274.8306, 6.5808) -> (194.8306, 6.5808)
  line L12 (274.8306, 12.5808) -> (274.8306, 6.5808)
  line L13 (322.8306, 12.5808) -> (274.8306, 12.5808)
  line L14 (322.8306, 27.5808) -> (322.8306, 12.5808)
  line L15 (328.8306, 27.5808) -> (322.8306, 27.5808)
  line L16 (328.8306, 47.5808) -> (328.8306, 27.5808)
  line L17 (322.8306, 47.5808) -> (328.8306, 47.5808)
  line L18 (322.8306, 77.5808) -> (322.8306, 47.5808)
  line L19 (328.8306, 77.5808) -> (322.8306, 77.5808)
  line L20 (328.8306, 97.5808) -> (328.8306, 77.5808)
  line L21 (322.8306, 97.5808) -> (328.8306, 97.5808)
  line L22 (322.8306, 112.5808) -> (322.8306, 97.5808)
  line L23 (274.8306, 112.5808) -> (322.8306, 112.5808)
  line L24 (274.8306, 118.5808) -> (274.8306, 112.5808)
  line L25 (194.8306, 118.5808) -> (274.8306, 118.5808)
  line L26 (194.8306, 112.5808) -> (194.8306, 118.5808)
  line L27 (140.8306, 112.5808) -> (194.8306, 112.5808)
  line L28 (140.8306, 118.5808) -> (140.8306, 112.5808)
  line L29 (60.8306, 118.5808) -> (140.8306, 118.5808)
  line L30 (60.8306, 112.5808) -> (60.8306, 118.5808)
  line L31 (12.8306, 112.5808) -> (60.8306, 112.5808)
  line L32 (12.8306, 97.5808) -> (12.8306, 112.5808)
  line L33 (6.8306, 97.5808) -> (12.8306, 97.5808)
  line L34 (6.8306, 77.5808) -> (6.8306, 97.5808)
  line L35 (12.8306, 77.5808) -> (6.8306, 77.5808)
  line L36 (12.8306, 47.5808) -> (12.8306, 77.5808)
  line L37 (235.1305, 51.5808) -> (235.1305, 53.2308)
  line L38 (232.1305, 53.2308) -> (232.1305, 51.5808)
  line L39 (229.7805, 53.2308) -> (232.1305, 53.2308)
  line L40 (228.6805, 70.8308) -> (228.6805, 54.3308)
  line L41 (232.1305, 71.9308) -> (229.7805, 71.9308)
  line L42 (232.1305, 73.5808) -> (232.1305, 71.9308)
  line L43 (235.1305, 71.9308) -> (235.1305, 73.5808)
  line L44 (237.4805, 71.9308) -> (235.1305, 71.9308)
  line L45 (238.5805, 54.3308) -> (238.5805, 70.8308)
  line L46 (235.1305, 53.2308) -> (237.4805, 53.2308)
  line L47 (204.3306, 55.0808) -> (204.3306, 80.0808)
  line L48 (131.3306, 55.0808) -> (204.3306, 55.0808)
  line L49 (131.3306, 80.0808) -> (131.3306, 55.0808)
  line L50 (204.3306, 80.0808) -> (131.3306, 80.0808)
  line L51 (270.6055, 53.2308) -> (272.9555, 53.2308)
  line L52 (270.6055, 51.5808) -> (270.6055, 53.2308)
  line L53 (267.6055, 53.2308) -> (267.6055, 51.5808)
  line L54 (265.2555, 53.2308) -> (267.6055, 53.2308)
  line L55 (264.1555, 70.8308) -> (264.1555, 54.3308)
  line L56 (267.6055, 71.9308) -> (265.2555, 71.9308)
  line L57 (267.6055, 73.5808) -> (267.6055, 71.9308)
  line L58 (270.6055, 71.9308) -> (270.6055, 73.5808)
  line L59 (272.9555, 71.9308) -> (270.6055, 71.9308)
  line L60 (274.0555, 54.3308) -> (274.0555, 70.8308)
  line L61 (48.6306, 49.0808) -> (48.6306, 76.0808)
  line L62 (35.6306, 49.0808) -> (48.6306, 49.0808)
  line L63 (35.6306, 76.0808) -> (35.6306, 49.0808)
  line L64 (48.6306, 76.0808) -> (35.6306, 76.0808)
  line L65 (295.8805, 54.5308) -> (295.8805, 70.6308)
  line L66 (293.4805, 54.5308) -> (295.8805, 54.5308)
  line L67 (293.4805, 70.6308) -> (293.4805, 54.5308)
  line L68 (295.8805, 70.6308) -> (293.4805, 70.6308)
  line L69 (25.5806, 107.0808) -> (25.5806, 91.5808)
  line L70 (25.5806, 91.5808) -> (20.0806, 91.5808)
  line L71 (20.0806, 91.5808) -> (20.0806, 107.0808)
  line L72 (14.8306, 107.0808) -> (30.8306, 107.0808)
  line L73 (30.8306, 112.5808) -> (14.8306, 112.5808)
  line L74 (30.8306, 107.0808) -> (30.8306, 112.5808)
  line L75 (14.8306, 112.5808) -> (14.8306, 107.0808)
  circle C1 centre (22.8306, 27.5808) radius 2.05
  circle C2 centre (312.8306, 27.5808) radius 2.05
  circle C3 centre (312.8306, 97.5808) radius 2.05
  arc A1 centre (233.6305, 51.5808) radius 1.5 clockwise from (235.1305, 51.5808) to (232.1305, 51.5808)
  arc A2 centre (229.7805, 54.3308) radius 1.1 clockwise from (229.7805, 53.2308) to (228.6805, 54.3308)
  arc A3 centre (229.7805, 70.8308) radius 1.1 clockwise from (228.6805, 70.8308) to (229.7805, 71.9308)
  arc A4 centre (233.6305, 73.5808) radius 1.5 clockwise from (232.1305, 73.5808) to (235.1305, 73.5808)
  arc A5 centre (237.4805, 70.8308) radius 1.1 clockwise from (237.4805, 71.9308) to (238.5805, 70.8308)
  arc A6 centre (237.4805, 54.3308) radius 1.1 clockwise from (238.5805, 54.3308) to (237.4805, 53.2308)
  circle C4 centre (130.3306, 52.0808) radius 1.5
  circle C5 centre (135.3306, 33.8308) radius 3
  circle C6 centre (150.3306, 33.8308) radius 3
  circle C7 centre (130.3306, 83.0808) radius 1.5
  arc A7 centre (269.1055, 51.5808) radius 1.5 clockwise from (270.6055, 51.5808) to (267.6055, 51.5808)
  arc A8 centre (265.2555, 54.3308) radius 1.1 clockwise from (265.2555, 53.2308) to (264.1555, 54.3308)
  arc A9 centre (265.2555, 70.8308) radius 1.1 clockwise from (264.1555, 70.8308) to (265.2555, 71.9308)
  arc A10 centre (269.1055, 73.5808) radius 1.5 clockwise from (267.6055, 73.5808) to (270.6055, 73.5808)
  arc A11 centre (272.9555, 70.8308) radius 1.1 clockwise from (272.9555, 71.9308) to (274.0555, 70.8308)
  arc A12 centre (272.9555, 54.3308) radius 1.1 clockwise from (274.0555, 54.3308) to (272.9555, 53.2308)
  circle C8 centre (205.3306, 83.0808) radius 1.5
  circle C9 centre (200.3306, 33.8308) radius 3
  circle C10 centre (88.4306, 62.5808) radius 11
  circle C11 centre (185.3306, 33.8308) radius 3
  circle C12 centre (205.3306, 52.0808) radius 1.5
  circle C13 centre (22.8306, 97.5808) radius 2.5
